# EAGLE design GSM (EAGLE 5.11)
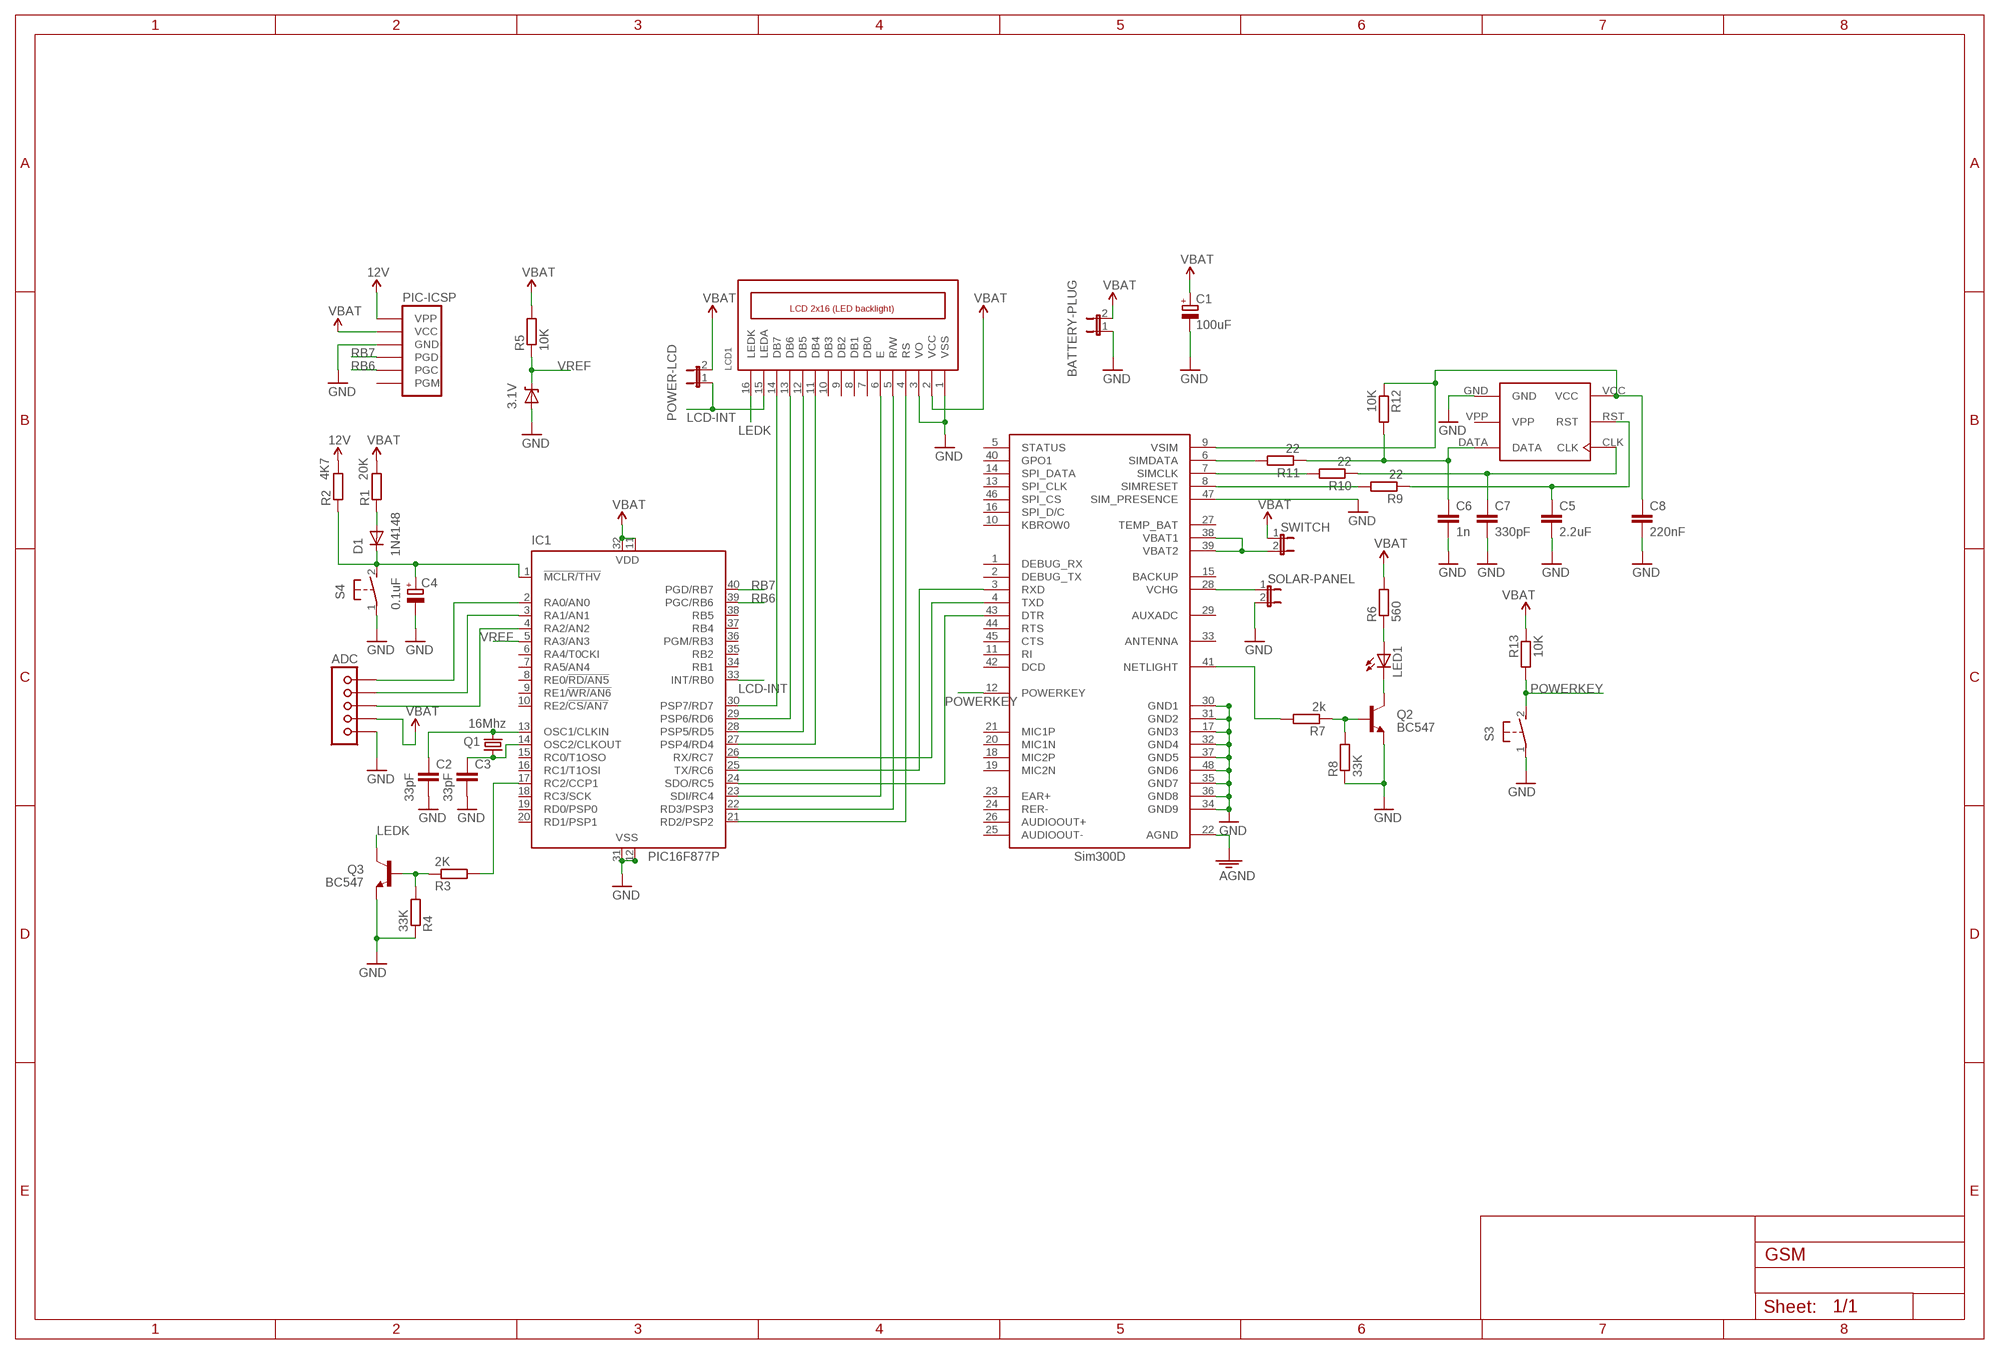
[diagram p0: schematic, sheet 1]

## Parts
3.1V  DIODE-ZENERPTH  [DIODE-ZENER]
ADC  KLEMES  [KLEMES]
BATTERY-PLUG  JP1E  [JP1]
C1  100uF  CPOL-EUE2.5-7  [E2,5-7]
C2  33pF  C-EU025-025X050  [C025-025X050]
C3  33pF  C-EU025-025X050  [C025-025X050]
C4  0.1uF  CPOL-EUE2-5  [E2-5]
C5  2.2uF  C-EU025-025X050  [C025-025X050]
C6  1n  C-EU025-025X050  [C025-025X050]
C7  330pF  C-EU025-025X050  [C025-025X050]
C8  220nF  C-EU025-025X050  [C025-025X050]
D1  1N4148  DIODE1N4148  [DIODE-1N4148]
IC1  PIC16F877P  [DIL40]
LCD1  LCD_2X16_SIL  [HY-1602F]
LED1  LEDSFH482  [SFH482]
PIC-ICSP  PIC-ICSP  [PIC-ICSP]
POWER-LCD  JP1E  [JP1]
Q1  16Mhz  CRYSTALHC49US  [HC49US]
Q2  BC547  TRANSISTOR_NPNSOT23  [SOT23]
Q3  BC547  TRANSISTOR_NPNSOT23  [SOT23]
R1  20K  R-EU_0207/12  [0207/12]
R2  4K7  R-EU_0207/12  [0207/12]
R3  2K  R-EU_0207/12  [0207/12]
R4  33K  R-EU_0207/12  [0207/12]
R5  10K  R-EU_0207/12  [0207/12]
R6  560  R-EU_0207/12  [0207/12]
R7  2k  R-EU_0207/12  [0207/12]
R8  33K  R-EU_0207/12  [0207/12]
R9  22  R-EU_0207/12  [0207/12]
R10  22  R-EU_0207/12  [0207/12]
R11  22  R-EU_0207/12  [0207/12]
R12  10K  R-EU_0207/12  [0207/12]
R13  10K  R-EU_0207/12  [0207/12]
S3  31-XX  [B3F-31XX]
S4  31-XX  [B3F-31XX]
SOLAR-PANEL  JP1E  [JP1]
SWITCH  JP1E  [JP1]
U$1  SIM300D  [SIM300D]
U$4  SIM-HOLDER  [SIM-HOLDER]

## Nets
12V: PIC-ICSP.P$12(VPP) R2.2
GND: 3.1V.P$2(A) ADC.P$10 BATTERY-PLUG.1 C1.- C2.2 C3.2 C4.- C5.2 C6.2 C7.2 C8.2 IC1.12(VSS) IC1.31(VSS) LCD1.1(VSS) LCD1.3(VO) PIC-ICSP.P$7(GND) Q2.2(E) Q3.2(E) R4.1 R8.1 S3.1(P) S4.1(P) SOLAR-PANEL.2 U$1.17(GND3) U$1.22(AGND) U$1.30(GND1) U$1.31(GND2) U$1.32(GND4) U$1.34(GND9) U$1.35(GND7) U$1.36(GND8) U$1.37(GND5) U$1.47(SIM_PRESENCE) U$1.48(GND6) U$4.GND ; supply symbol labelled AGND
LCD-INT: IC1.33(INT/RB0) LCD1.15(LEDA) POWER-LCD.1
LEDK: LCD1.16(LEDK) Q3.3(C)
N$1: IC1.30(PSP7/RD7) LCD1.14(DB7)
N$2: IC1.29(PSP6/RD6) LCD1.13(DB6)
N$3: SOLAR-PANEL.1 U$1.28(VCHG)
N$4: D1.A R1.1
N$5: C2.1 IC1.13(OSC1/CLKIN) Q1.2
N$6: C3.1 IC1.14(OSC2/CLKOUT) Q1.1
N$7: IC1.26(RX/RC7) U$1.4(TXD)
N$8: C4.+ D1.C IC1.1(!MCLR/THV) R2.1 S4.2(S)
N$9: R10.2 U$1.7(SIMCLK)
N$10: C5.1 R9.1 U$4.RST
N$11: R11.2 U$1.6(SIMDATA)
N$12: C7.1 R10.1 U$4.CLK
N$14: Q2.1(B) R7.1 R8.2
N$15: LED1.K(C) Q2.3(C)
N$16: LED1.A R6.1
N$17: IC1.28(PSP5/RD5) LCD1.12(DB5)
N$18: IC1.27(PSP4/RD4) LCD1.11(DB4)
N$19: IC1.23(SDI/RC4) LCD1.6(E)
N$20: IC1.21(RD2/PSP2) LCD1.4(RS)
N$21: R7.2 U$1.41(NETLIGHT)
N$22: C6.1 R11.1 R12.2 U$4.DATA
N$23: C8.1 R12.1 U$1.9(VSIM) U$4.VCC
N$24: R9.2 U$1.8(SIMRESET)
N$25: IC1.22(RD3/PSP3) LCD1.5(R/W)
N$26: IC1.25(TX/RC6) U$1.3(RXD)
N$27: ADC.P$6 IC1.2(RA0/AN0)
N$28: ADC.P$7 IC1.3(RA1/AN1)
N$29: ADC.P$8 IC1.4(RA2/AN2)
N$30: IC1.24(SDO/RC5) U$1.43(DTR)
N$31: IC1.17(RC2/CCP1) R3.2
N$32: Q3.1(B) R3.1 R4.2
N$33: SWITCH.2 U$1.38(VBAT1) U$1.39(VBAT2)
POWERKEY: R13.2 S3.2(S) U$1.12(POWERKEY)
RB6: IC1.39(PGC/RB6) PIC-ICSP.P$8(PGC)
RB7: IC1.40(PGD/RB7) PIC-ICSP.P$9(PGD)
VBAT: ADC.P$9 BATTERY-PLUG.2 C1.+ IC1.11(VDD) IC1.32(VDD) LCD1.2(VCC) PIC-ICSP.P$11(VCC) POWER-LCD.2 R1.2 R5.2 R6.2 R13.1 SWITCH.1
VREF: 3.1V.P$1(C) IC1.5(RA3/AN3) R5.1
Unconnected: IC1.6(RA4/T0CKI) IC1.7(RA5/AN4) IC1.8(RE0/!RD/AN5) IC1.9(RE1/!WR/AN6) IC1.10(RE2/!CS/AN7) IC1.15(RC0/T1OSO) IC1.16(RC1/T1OSI) IC1.18(RC3/SCK) IC1.19(RD0/PSP0) IC1.20(RD1/PSP1) IC1.34(RB1) IC1.35(RB2) IC1.36(PGM/RB3) IC1.37(RB4) IC1.38(RB5) LCD1.7(DB0) LCD1.8(DB1) LCD1.9(DB2) LCD1.10(DB3) PIC-ICSP.P$10(PGM) U$1.1(DEBUG_RX) U$1.2(DEBUG_TX) U$1.5(STATUS) U$1.10(KBROW0) U$1.11(RI) U$1.13(SPI_CLK) U$1.14(SPI_DATA) U$1.15(BACKUP) U$1.16(SPI_D/C) U$1.18(MIC2P) U$1.19(MIC2N) U$1.20(MIC1N) U$1.21(MIC1P) U$1.23(EAR+) U$1.24(RER-) U$1.25(AUDIOOUT-) U$1.26(AUDIOOUT+) U$1.27(TEMP_BAT) U$1.29(AUXADC) U$1.33(ANTENNA) U$1.40(GPO1) U$1.42(DCD) U$1.44(RTS) U$1.45(CTS) U$1.46(SPI_CS)

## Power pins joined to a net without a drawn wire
VPP: U$4.VPP

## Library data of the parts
3.1V = SparkFun:DIODE-ZENER: Zener Diode
ADC = candrian:KLEMES
BATTERY-PLUG POWER-LCD SOLAR-PANEL SWITCH = jumper:JP1E: JUMPER
C1 C4 = rcl:CPOL-EU: POLARIZED CAPACITOR, European symbol
C2 C3 C5-C8 = rcl:C-EU: CAPACITOR, European symbol
D1 = SparkFun:DIODE: Diode
IC1 = microchip:PIC16F87*: MICROCONTROLLER; MF: MICROCHIP; MPN: PIC16F877-04/P; OC_FARNELL: 9761349; OC_NEWARK: 61K3463
LCD1 = lcd_2x16_led_backlight:LCD_2X16_SIL
LED1 = led:LED: LED
PIC-ICSP = Andrianakis:PIC-ICSP
Q1 = SparkFun:CRYSTAL: Crystals
Q2 Q3 = SparkFun:TRANSISTOR_NPN: Transistor NPN BJT configuration in SOT23 package. MMBT2222 is the common NPN we use. Double check BCE configuration again layout.
R1-R13 = rcl:R-EU_: RESISTOR, European symbol
S3 S4 = switch-omron:31-XX: OMRON SWITCH; MPN: B3F-3100; OC_FARNELL: 959704; OC_NEWARK: 36M3582
U$1 = Andrianakis:SIM300D: Designed by Andrianakis Charalampos email: microtro@gmail.com
U$4 = Andrianakis:SIM-HOLDER

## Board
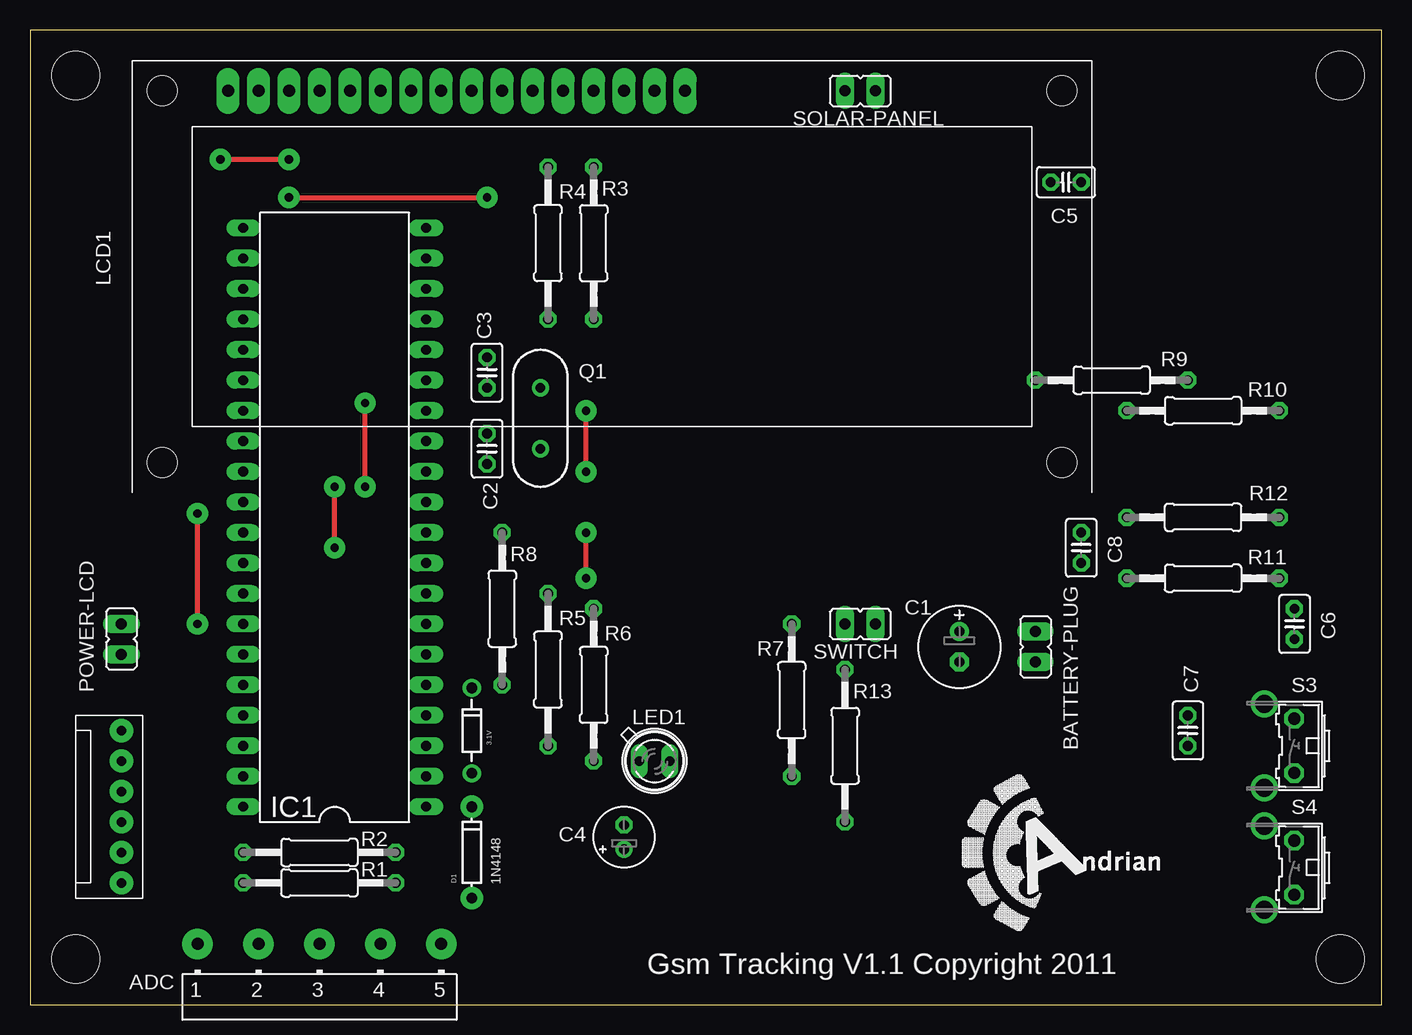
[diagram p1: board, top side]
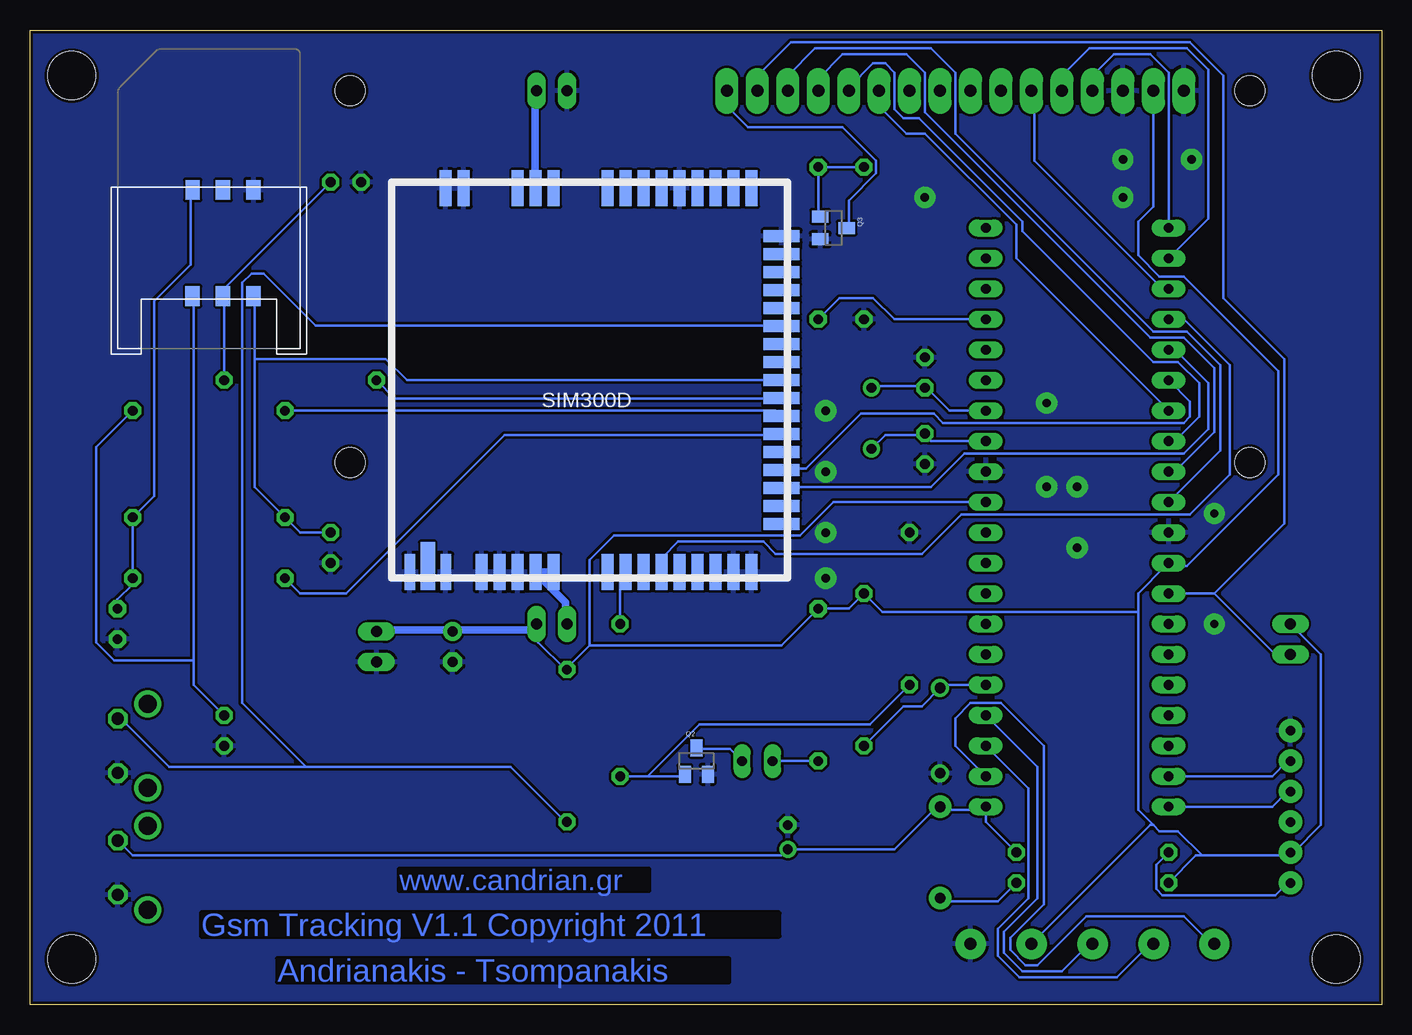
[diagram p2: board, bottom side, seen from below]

Size 112.7 x 81.27 mm. Coordinates in mm from the lower left corner, seen from the top.
Outline: 0,0 112.7,0 112.7,81.27 0,81.27 0,0
Copper layers (1*16): Top 0.035mm / dielectric 1.5mm / Bottom 0.035mm
Design rules "SparkFun": minimum track width 8mil, minimum drill 20mil, track to track 8mil, track to pad 8mil, pad to pad 8mil, via to via 8mil, smd to smd 8mil, copper to edge 10mil, drill to drill 8mil, minimum pad ring 12mil, minimum via ring 10mil, stop-mask expansion 4mil, vias tented up to drill 25mil, thermal gap 10mil
Holes 4 mm at 3.81,77.47 3.81,3.81 109.22,77.47 109.22,3.81

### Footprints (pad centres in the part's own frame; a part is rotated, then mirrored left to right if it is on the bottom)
DIODE-ZENER = drill 0.9 round: P$1 -3.556,0; P$2 3.556,0
KLEMES = drill 1 pad 2.54 round: P$6 -10.16,1.27; P$7 -5.08,1.27; P$8 0,1.27; P$9 5.08,1.27; P$10 10.16,1.27
JP1 = drill 0.914 long: 1 0,-1.27; 2 0,1.27
E2,5-7 = drill 0.813 pad 1.6 round: + -1.27,0 | drill 0.813 pad 1.6 octagon: - 1.27,0
C025-025X050 = drill 0.813 octagon: 1 -1.27,0; 2 1.27,0
E2-5 = drill 0.813 pad 1.27 round: + -1.016,0 | drill 0.813 pad 1.27 octagon: - 1.016,0
DIODE-1N4148 = drill 0.9 pad 1.88 round: A -3.81,0; C 3.81,0
DIL40 = drill 0.813 long: 1 -24.13,-7.62; 2 -21.59,-7.62; 3 -19.05,-7.62; 4 -16.51,-7.62; 5 -13.97,-7.62; 6 -11.43,-7.62; 7 -8.89,-7.62; 8 -6.35,-7.62; 9 -3.81,-7.62; 10 -1.27,-7.62; 11 1.27,-7.62; 12 3.81,-7.62; 13 6.35,-7.62; 14 8.89,-7.62; 15 11.43,-7.62; 16 13.97,-7.62; 17 16.51,-7.62; 18 19.05,-7.62; 19 21.59,-7.62; 20 24.13,-7.62; 21 24.13,7.62; 22 21.59,7.62; 23 19.05,7.62; 24 16.51,7.62; 25 13.97,7.62; 26 11.43,7.62; 27 8.89,7.62; 28 6.35,7.62; 29 3.81,7.62; 30 1.27,7.62; 31 -1.27,7.62; 32 -3.81,7.62; 33 -6.35,7.62; 34 -8.89,7.62; 35 -11.43,7.62; 36 -13.97,7.62; 37 -16.51,7.62; 38 -19.05,7.62; 39 -21.59,7.62; 40 -24.13,7.62
HY-1602F = drill 1 pad 1.93 long: 1 2.54,0; 2 5.08,0; 3 7.62,0; 4 10.16,0; 5 12.7,0; 6 15.24,0; 7 17.78,0; 8 20.32,0; 9 22.86,0; 10 25.4,0; 11 27.94,0; 12 30.48,0; 13 33.02,0; 14 35.56,0; 15 38.1,0; 16 40.64,0 | hole 2.5: -2.96,0; 72.04,0; -2.96,-31; 72.04,-31
SFH482 = drill 0.813 long: A -1.27,0; K 1.27,0
PIC-ICSP = drill 0.8 pad 1.93 round: P$7 -6.35,1.27; P$8 -3.81,1.27; P$9 -1.27,1.27; P$10 1.27,1.27; P$11 3.81,1.27; P$12 6.35,1.27
HC49US = drill 0.813 round: 1 -2.54,0; 2 2.54,0
SOT23 = smd 1 x 1.4: 1 -0.95,-1.1; 2 0.95,-1.1; 3 0,1.1
0207/12 = drill 0.813 octagon: 1 -6.35,0; 2 6.35,0
B3F-31XX = drill 1.016 octagon: 1 -2.261,-1.245; 2 2.261,-1.245 | drill 1.499 pad 2.159 round: 3 -3.505,1.245; 4 3.505,1.245
SIM300D = smd 3 x 1: 1 -16,12; 2 -16,10.5; 3 -16,9; 4 -16,7.5; 5 -16,6; 6 -16,4.5; 7 -16,3; 8 -16,1.5; 9 -16,0; 10 -16,-1.5; 11 -16,-3; 12 -16,-4.5; 13 -16,-6; 14 -16,-7.5; 15 -16,-9; 16 -16,-10.5; 17 -16,-12 | smd 1 x 3: 18 -13.5,-16; 19 -12,-16; 20 -10.5,-16; 21 -9,-16; 22 -7.5,-16; 23 -6,-16; 24 -4.5,-16; 25 -3,-16; 26 -1.5,-16; 27 3,-16; 28 4.5,-16; 29 6,-16; 30 10.5,-16; 31 12,-16; 35 9,16; 36 7.5,16; 37 6,16; 38 4.5,16; 39 3,16; 40 -1.5,16; 41 -3,16; 42 -4.5,16; 43 -6,16; 44 -7.5,16; 45 -9,16; 46 -10.5,16; 47 -12,16; 48 -13.5,16 | smd 0.9 x 3: 32 15,16; 34 12,16 | smd 1.2 x 4: 33 13.5,15.5
SIM-HOLDER = smd 1.65 x 1.2: CLK -8.23,2.63; DATA 0.62,2.62; GND 0.62,-2.46; RST -8.23,0.09; VCC -8.23,-2.45; VPP 0.62,0.08

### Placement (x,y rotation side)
3.1V  36.83,22.86 270 top
ADC  24.13,3.81 0 top
BATTERY-PLUG  83.82,29.84 0 top
C1  77.47,29.84 270 top
C2  38.1,46.35 270 top
C3  38.1,52.7 90 top
C4  49.53,13.97 90 top
C5  86.36,68.58 180 top
C6  105.41,31.75 270 top
C7  96.52,22.86 270 top
C8  87.63,38.1 270 top
D1  36.83,12.7 90 top
IC1  25.4,40.64 90 top
LCD1  13.97,76.2 0 top
LED1  52.07,20.32 0 top
PIC-ICSP  6.35,16.51 270 top
POWER-LCD  7.62,30.48 0 top
Q1  42.55,48.9 270 top
Q2  57.15,20.32 0 bottom
Q3  45.72,64.77 270 bottom
R1  24.13,10.16 180 top
R2  24.13,12.7 180 top
R3  46.99,63.5 270 top
R4  43.18,63.5 90 top
R5  43.18,27.94 90 top
R6  46.99,26.67 90 top
R7  63.5,25.4 90 top
R8  39.37,33.02 270 top
R9  90.17,52.07 180 top
R10  97.79,49.53 180 top
R11  97.79,35.56 180 top
R12  97.79,40.64 0 top
R13  67.94,21.59 270 top
S3  104.14,21.59 90 top
S4  104.14,11.43 90 top
SOLAR-PANEL  69.22,76.2 90 top
SWITCH  69.22,31.75 90 top
U$1  66.04,52.07 180 bottom
U$2  [CANDRIAN-LOGO]  86.99,11.43 0 top
U$4  96.52,67.31 90 bottom

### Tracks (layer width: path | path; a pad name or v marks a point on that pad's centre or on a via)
12V
  Bottom 0.203: R2.2 18.8,11.68 18.8,9.65 18.29,9.14 8.89,9.14 7.87,10.16 PIC-ICSP.P$12
GND  (via drill 0.7 pad 1.78)
  Top 0.406: v15.88,70.48 v21.59,70.48 | v21.59,67.31 v38.1,67.31 | v13.97,31.75 v13.97,40.96 | v25.4,38.1 v25.4,43.18 | v46.36,35.56 v46.36,39.37 | v27.94,43.18 v27.94,50.16 | v46.36,44.45 v46.36,49.53
  pour Bottom: 0,81.28 113.03,81.28 113.03,0 0,0
LCD-INT
  Bottom 0.203: 13.97,34.29 IC1.33 | 13.97,34.29 8.89,29.21 POWER-LCD.1 | LCD1.15 52.07,77.47 49.28,80.26 16,80.26 13.21,77.47 13.21,58.93 8.13,53.85 8.13,40.13 13.97,34.29
LEDK
  Bottom 0.203: LCD1.16 54.61,74.93 52.83,73.15 44.96,73.15 42.16,70.36 42.16,69.34 44.45,67.06 44.45,64.77 Q3.3
N$1
  Bottom 0.203: IC1.30 13.46,46.23 13.46,53.34 16.26,56.13 19.05,56.13 35.56,72.64 35.56,77.72 37.59,79.76 47.24,79.76 49.53,77.47 LCD1.14
N$2
  Bottom 0.203: IC1.29 17.27,44.45 13.97,47.75 13.97,53.09 16.51,55.63 19.3,55.63 38.1,74.42 38.1,77.72 39.62,79.25 44.96,79.25 46.99,77.22 LCD1.13
N$3
  Bottom 0.203: U$1.28 70.61,68.07 | 70.61,76.2 SOLAR-PANEL.1
  Bottom 0.61: 70.61,68.07 70.61,76.2
N$4
  Bottom 0.203: R1.1 32,8.64 36.58,8.64 D1.A
N$5
  Bottom 0.203: IC1.13 37.59,46.99 38.1,47.5 | 38.1,47.5 41.4,47.5 Q1.2 | 38.1,47.5 C2.1
N$6
  Bottom 0.203: IC1.14 36.07,49.53 38.1,51.56 | 38.1,51.56 42.42,51.56 Q1.1 | 38.1,51.56 C3.1
N$7
  Bottom 0.203: IC1.26 16,50.29 16,49.02 16.51,48.51 36.58,48.51 37.34,49.28 43.43,49.28 48.01,44.7 50.04,44.7 U$1.4
N$8
  Bottom 0.203: R2.1 33.02,15.24 33.02,16.26 | 37.34,16.26 37.08,16.51 D1.C 37.34,16.26 | 37.34,16.26 40.64,12.95 C4.+ 50.04,12.45 104.14,12.45 S4.2 | 33.02,16.26 37.34,16.26 | 33.02,16.26 IC1.1
N$9
  Bottom 0.203: R10.2 50.55,49.53 50.29,49.28 U$1.7
N$10
  Bottom 0.203: R9.1 96.52,58.93 U$4.RST 96.52,59.18 96.52,59.69 C5.1
N$11
  Bottom 0.203: R11.2 90.17,34.29 86.36,34.29 73.15,47.5 50.29,47.5 U$1.6
N$12
  Bottom 0.203: 99.06,28.7 99.06,26.67 C7.1 | 99.06,28.7 99.06,58.93 U$4.CLK | R10.1 107.19,46.48 107.19,30.23 105.66,28.7 99.06,28.7
N$14
  Bottom 0.203: 61.21,19.05 R7.1 | 61.21,19.05 58.17,19.05 Q2.1 | R8.2 42.67,23.37 56.9,23.37 61.21,19.05
N$15
  Bottom 0.203: LED1.K 54.36,21.34 57.15,21.34 Q2.3
N$16
  Bottom 0.203: R6.1 LED1.A
N$17
  Bottom 0.203: IC1.28 17.27,46.99 15.24,49.02 15.24,51.82 17.02,53.59 19.05,53.59 29.97,64.52 29.97,65.28 38.61,73.91 39.88,73.91 40.64,74.68 40.64,77.72 41.4,78.49 42.42,78.49 44.45,76.45 LCD1.12
N$18
  Bottom 0.203: IC1.27 30.48,62.23 30.48,65.02 38.1,72.64 39.62,72.64 41.91,74.93 LCD1.11
N$19
  Bottom 0.203: IC1.23 18.29,59.69 28.96,70.36 28.96,75.95 LCD1.6
N$20
  Bottom 0.203: IC1.21 17.78,77.72 19.3,79.25 22.35,79.25 24.13,77.47 LCD1.4
N$21
  Bottom 0.203: R7.2 63.5,35.81 63.25,36.07 U$1.41
N$22
  Bottom 0.203: C6.1 105.41,33.78 104.14,35.05 R11.1 R12.2 102.36,42.42 102.36,58.67 99.31,61.72 99.31,67.82 U$4.DATA
N$23
  Bottom 0.203: 93.98,53.85 93.98,43.18 R12.1 90.17,39.37 C8.1 | 93.98,53.85 93.98,58.93 U$4.VCC | 93.98,53.85 83.06,53.85 81.28,52.07 U$1.9
N$24
  Bottom 0.203: R9.2 82.3,50.55 50.29,50.55 U$1.8
N$25
  Bottom 0.203: IC1.22 14.48,65.53 14.48,77.98 16.26,79.76 24.38,79.76 26.67,77.47 LCD1.5
N$26
  Bottom 0.203: IC1.25 17.27,54.61 14.48,51.82 14.48,48.01 16.51,45.97 34.8,45.97 37.59,43.18 50.04,43.18 U$1.3
N$27
  Bottom 0.203: IC1.2 35.56,21.59 35.56,23.88 34.29,25.15 31.75,25.15 28.19,21.59 28.19,8.38 30.99,5.59 30.99,4.57 29.72,3.3 28.7,3.3 24.64,7.37 16.51,7.37 14.22,5.08 ADC.P$6
N$28
  Bottom 0.203: IC1.3 29.46,18.03 29.46,8.89 32,6.35 32,4.06 30.23,2.29 22.1,2.29 19.3,5.08 ADC.P$7
N$29
  Bottom 0.203: IC1.4 28.7,19.81 28.7,8.89 31.5,6.1 31.5,4.32 29.97,2.79 26.67,2.79 24.38,5.08 ADC.P$8
N$30
  Bottom 0.203: IC1.24 16.51,57.15 12.7,53.34 12.7,44.2 16,40.89 35.05,40.89 38.35,37.59 50.55,37.59 51.56,38.61 58.67,38.61 59.94,37.34 59.94,36.32 U$1.43
N$31
  Bottom 0.203: IC1.17 40.64,57.15 42.42,58.93 45.21,58.93 R3.2
N$32
  Bottom 0.203: Q3.1 46.99,65.79 R3.1 R4.2
N$33
  Bottom 0.203: 69.09,36.07 U$1.39 | 70.36,36.07 U$1.38 70.61,36.07 | SWITCH.2 68.07,31.75
  Bottom 0.61: 70.36,36.07 69.09,36.07 | 68.07,31.75 68.07,33.53 70.61,36.07
POWERKEY
  Bottom 0.203: 89.66,19.81 101.09,19.81 105.16,23.88 S3.2 | 89.66,19.81 72.64,19.81 68.07,15.24 R13.2 | 89.66,19.81 95,25.15 95,60.2 94.23,60.96 93.22,60.96 88.9,56.64 50.29,56.64 U$1.12
RB6
  Bottom 0.203: IC1.39 9.14,19.05 7.87,20.32 PIC-ICSP.P$8
RB7
  Bottom 0.203: IC1.40 9.14,16.51 7.87,17.78 PIC-ICSP.P$9
VBAT
  Bottom 0.203: 83.82,31.24 BATTERY-PLUG.2 | 68.07,27.94 70.36,30.23 70.36,31.24 | 70.36,31.24 70.36,31.75 SWITCH.1 70.36,31.24 | IC1.11 45.72,41.91 48.51,39.12 64.01,39.12 66.04,37.08 66.04,29.97 | 66.04,29.97 68.07,27.94 | 68.07,27.94 R13.1 | 66.04,29.97 50.04,29.97 R6.2 44.45,33.02 R5.2 41.66,32.77 20.32,32.77 | 77.47,31.24 C1.+ | R1.2 15.49,12.45 14.99,12.45 | 14.99,12.45 7.87,12.45 PIC-ICSP.P$11 7.37,12.7 5.08,14.99 5.08,29.21 POWER-LCD.2 | 18.03,36.58 20.32,34.29 20.32,32.77 | 20.32,32.77 20.32,16.26 19.05,14.99 | 19.05,14.99 18.54,14.48 17.02,14.48 14.99,12.45 | LCD1.2 19.05,66.55 20.32,65.28 20.32,62.48 18.54,60.71 16.51,60.71 8.64,52.83 8.64,44.2 16.26,36.58 18.03,36.58 | 18.03,36.58 IC1.32 | ADC.P$9 19.3,14.99 19.05,14.99
  Bottom 0.61: 83.82,31.24 77.47,31.24 70.36,31.24
VREF
  Bottom 0.203: IC1.5 36.58,26.67 3.1V.P$1 38.35,24.89 39.88,24.89 R5.1

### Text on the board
Bottom: www.candrian.gr | Gsm Tracking V1.1 Copyright 2011 | Andrianakis - Tsompanakis
tNames: Gsm Tracking V1.1 Copyright 2011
